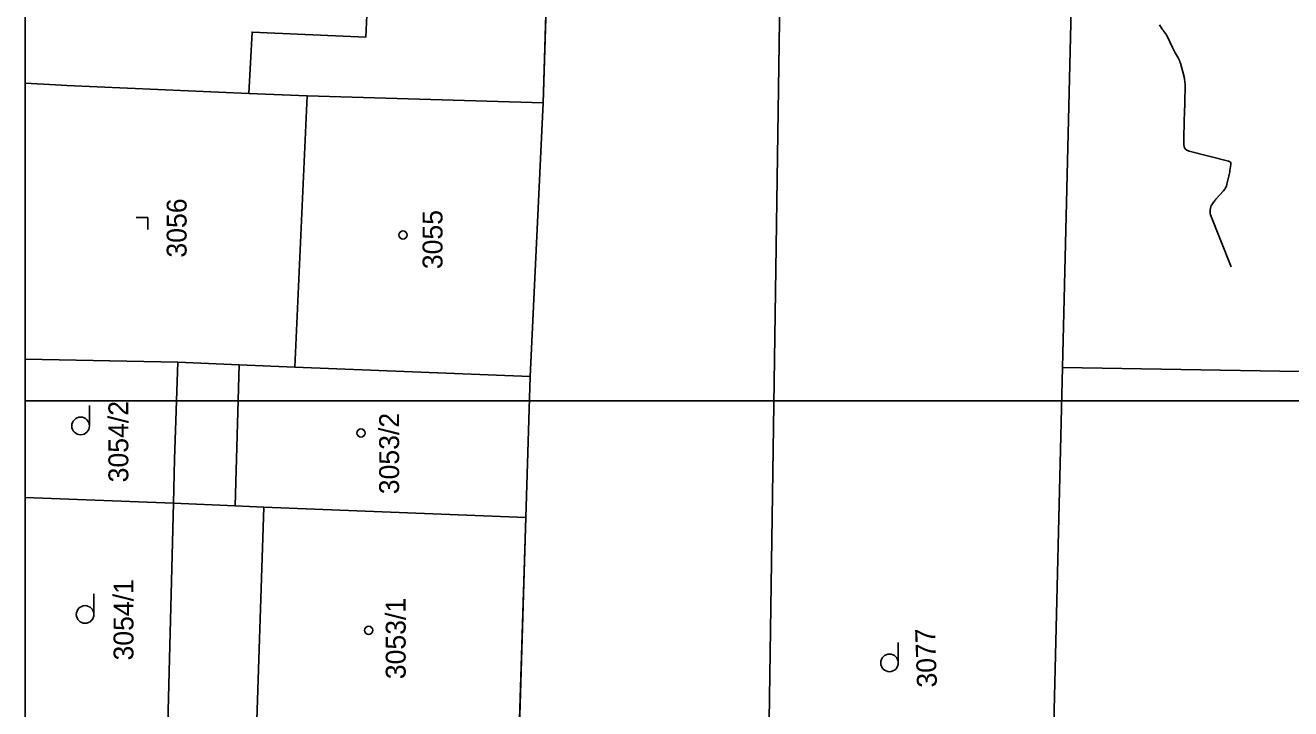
# Model space of a CAD drawing. Extents: x -534410 to -534262, y -1190162 to -1189584.
# Drawn here: x -534410.1 to -534356.1, y -1190017.6 to -1189988.4 of the extents above; entities that cross this region are included whole.
import ezdxf

# ---------------------------------------------------------------- set-up
doc = ezdxf.new("R2010")
doc.units = 0
for name, color, linetype in [('31', 7, 'Continuous'), ('_rámeček', 7, 'Continuous'), ('_rámeček_mřížka', 7, 'Continuous'), ('Hranice parcel', 7, 'Continuous'), ('Parcelní čísla', 7, 'Continuous'), ('Polygon budovy', 7, 'Continuous'), ('Značky budov', 7, 'Continuous'), ('Značky kultur', 7, 'Continuous')]:
    doc.layers.add(name, color=color, linetype=linetype)

msp = doc.modelspace()

# ---------------------------------------------------------------- linework, layer by layer
at = {"layer": '31'}
msp.add_lwpolyline([(-534361.693, -1189988.419), (-534361.578, -1189988.591), (-534361.56, -1189988.617), (-534361.541, -1189988.643), (-534361.522, -1189988.669), (-534361.503, -1189988.694), (-534361.423, -1189988.794), (-534361.404, -1189988.82), (-534361.387, -1189988.847), (-534361.371, -1189988.874), (-534361.357, -1189988.903), (-534361.138, -1189989.387), (-534361.112, -1189989.444), (-534361.083, -1189989.499), (-534361.054, -1189989.555), (-534361.022, -1189989.609), (-534360.894, -1189989.824), (-534360.864, -1189989.879), (-534360.838, -1189989.935), (-534360.816, -1189989.993), (-534360.798, -1189990.053), (-534360.644, -1189990.634), (-534360.62, -1189990.739), (-534360.604, -1189990.846), (-534360.595, -1189990.954), (-534360.595, -1189991.063), (-534360.614, -1189991.654), (-534360.615, -1189991.685), (-534360.615, -1189991.717), (-534360.616, -1189991.749), (-534360.616, -1189991.781), (-534360.616, -1189991.908), (-534360.616, -1189991.94), (-534360.617, -1189991.971), (-534360.618, -1189992.003), (-534360.618, -1189992.035), (-534360.639, -1189992.626), (-534360.642, -1189992.735), (-534360.644, -1189992.845), (-534360.646, -1189992.954), (-534360.647, -1189993.063), (-534360.648, -1189993.524), (-534360.635, -1189993.626), (-534360.594, -1189993.707), (-534360.525, -1189993.767), (-534360.429, -1189993.806), (-534358.748, -1189994.231), (-534358.697, -1189994.252), (-534358.663, -1189994.285), (-534358.646, -1189994.328), (-534358.646, -1189994.384), (-534358.682, -1189994.628), (-534358.691, -1189994.689), (-534358.702, -1189994.75), (-534358.714, -1189994.81), (-534358.728, -1189994.871), (-534358.811, -1189995.222), (-534358.834, -1189995.298), (-534358.866, -1189995.37), (-534358.907, -1189995.437), (-534358.957, -1189995.499), (-534359.283, -1189995.859), (-534359.305, -1189995.885), (-534359.327, -1189995.911), (-534359.347, -1189995.938), (-534359.367, -1189995.966), (-534359.459, -1189996.103), (-534359.469, -1189996.12), (-534359.478, -1189996.138), (-534359.486, -1189996.156), (-534359.492, -1189996.174), (-534359.513, -1189996.25), (-534359.518, -1189996.27), (-534359.522, -1189996.289), (-534359.524, -1189996.308), (-534359.524, -1189996.328), (-534359.525, -1189996.436), (-534359.524, -1189996.461), (-534359.521, -1189996.485), (-534359.515, -1189996.508), (-534359.507, -1189996.531), (-534358.63, -1189998.754)], dxfattribs=at)
at = {"layer": '_rámeček'}
msp.add_line((-534410.126, -1189584.47), (-534410.126, -1190161.97), dxfattribs=at)
for points in [[(-534410.126, -1189899.47), (-534261.626, -1189899.47), (-534261.626, -1190004.47), (-534410.126, -1190004.47)], [(-534410.126, -1190004.47), (-534261.626, -1190004.47), (-534261.626, -1190109.47), (-534410.126, -1190109.47)]]:
    msp.add_lwpolyline(points, close=True, dxfattribs=at)
at = {"layer": '_rámeček_mřížka'}
for p, q in [((-534410.126, -1189584.47), (-534410.126, -1190161.97)), ((-534407.126, -1190004.47), (-534410.126, -1190004.47))]:
    msp.add_line(p, q, dxfattribs=at)
at = {"layer": 'Hranice parcel'}
for p, q in [((-534388.01, -1189991.75), (-534387.85, -1189986.52)), ((-534398.09, -1189991.44), (-534398.61, -1190003.03)), ((-534388.01, -1189991.75), (-534398.09, -1189991.44)), ((-534388.57, -1190003.43), (-534388.01, -1189991.75)), ((-534410.126, -1190002.694), (-534403.61, -1190002.82)), ((-534398.61, -1190003.03), (-534388.57, -1190003.43)), ((-534388.57, -1190003.43), (-534388.75, -1190009.46)), ((-534366.35, -1190024.04), (-534365.84, -1190003.05)), ((-534365.84, -1190003.05), (-534341.99, -1190003.45)), ((-534403.8, -1190008.85), (-534410.126, -1190008.598)), ((-534403.8, -1190008.85), (-534404.06, -1190018.82)), ((-534388.75, -1190009.46), (-534389.06, -1190019.44))]:
    msp.add_line(p, q, dxfattribs=at)
for points in [[(-534365.84, -1190003.05), (-534365.09, -1189972.48), (-534364.31, -1189951.16)], [(-534380.79, -1190075.34), (-534378.76, -1190045.09), (-534377.74, -1189975.71)], [(-534398.09, -1189991.44), (-534400.58, -1189991.34), (-534408.35, -1189991), (-534408.84, -1189990.98), (-534410.126, -1189990.907)], [(-534403.61, -1190002.82), (-534403.75, -1190006.97), (-534403.8, -1190008.85)], [(-534403.61, -1190002.82), (-534400.99, -1190002.93), (-534398.61, -1190003.03)], [(-534388.75, -1190009.46), (-534399.94, -1190009.01), (-534401.17, -1190008.96), (-534403.8, -1190008.85)]]:
    msp.add_lwpolyline(points, dxfattribs=at)
at = {"layer": 'Polygon budovy'}
for points in [[(-534397.05, -1189983.85), (-534395.35, -1189983.92), (-534395.59, -1189988.94), (-534400.44, -1189988.72), (-534400.58, -1189991.34), (-534398.09, -1189991.44), (-534388.01, -1189991.75), (-534387.85, -1189986.52), (-534387.71, -1189986.52), (-534387.44, -1189980.01), (-534391.9, -1189979.81), (-534391.84, -1189976.92), (-534396.75, -1189976.78)], [(-534398.61, -1190003.03), (-534388.57, -1190003.43), (-534388.01, -1189991.75), (-534398.09, -1189991.44)], [(-534400.99, -1190002.93), (-534401.17, -1190008.96), (-534399.94, -1190009.01), (-534388.75, -1190009.46), (-534388.57, -1190003.43), (-534398.61, -1190003.03)], [(-534399.91, -1190018.99), (-534389.06, -1190019.44), (-534388.75, -1190009.46), (-534399.94, -1190009.01), (-534400.27, -1190018.98)]]:
    msp.add_lwpolyline(points, close=True, dxfattribs=at)
at = {"layer": 'Značky budov'}
for centre in [(-534393.997, -1189997.387), (-534395.792, -1190005.847), (-534395.463, -1190014.273)]:
    msp.add_circle(centre, 0.175, dxfattribs=at)
at = {"layer": 'Značky kultur'}
for p, q in [((-534404.893, -1189996.647), (-534405.393, -1189996.647)), ((-534404.893, -1189997.148), (-534404.893, -1189996.647)), ((-534407.39, -1190005.544), (-534407.39, -1190004.669)), ((-534407.198, -1190013.596), (-534407.198, -1190012.721)), ((-534372.846, -1190015.666), (-534372.846, -1190014.791))]:
    msp.add_line(p, q, dxfattribs=at)
for centre in [(-534407.765, -1190005.544), (-534407.573, -1190013.596), (-534373.221, -1190015.666)]:
    msp.add_circle(centre, 0.375, dxfattribs=at)

# ---------------------------------------------------------------- texts
at = {"layer": 'Parcelní čísla'}
for s, rotation, p in [('3056', 90, (-534403.238, -1189998.355)), ('3055', 90, (-534392.31, -1189998.85)), ('3054/2', 90, (-534405.728, -1190007.955)), ('3053/2', 90, (-534394.164, -1190008.463)), ('3054/1', 90, (-534405.508, -1190015.564)), ('3053/1', 90, (-534393.884, -1190016.363)), ('3077', 92, (-534371.192, -1190016.705))]:
    msp.add_text(s, height=0.85, rotation=rotation, dxfattribs=at).set_placement(p)

doc.saveas('drawing.dxf')
